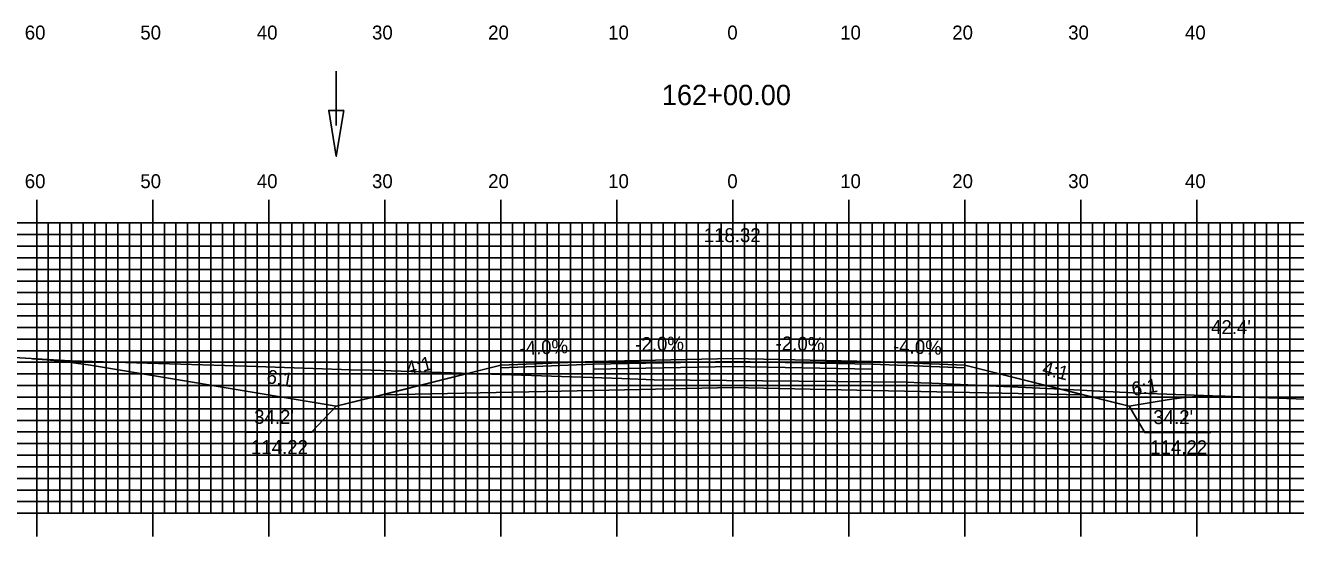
# Model space of a CAD drawing. Extents: x 1780286 to 1780629, y 442591 to 442811.
# Drawn here: x 1780390.9 to 1780500.4, y 442696.7 to 442740.7 of the extents above; entities that cross this region are included whole.
import ezdxf

# ---------------------------------------------------------------- set-up
doc = ezdxf.new("R2010")
doc.units = 0
for name, color, linetype in [('ANNOTATION', 7, 'Continuous'), ('D_Drainage_Ditch_Line', 7, 'Continuous'), ('D_Roadway_Centerline', 7, 'Continuous'), ('D_Roadway_Centerline_Text', 7, 'Continuous'), ('D_Roadway_Edge_Shoulder', 7, 'Continuous'), ('D_Roadway_Edge_TW', 7, 'Continuous'), ('D_Roadway_Pavement', 7, 'Continuous'), ('D_Roadway_SlopeLines', 7, 'Continuous'), ('D_Roadway_SubGrade', 7, 'Continuous'), ('D_Text_Standard', 7, 'Continuous'), ('H_V ANNOTATION', 7, 'Continuous'), ('MAJOR', 7, 'Continuous'), ('MINOR', 7, 'Continuous'), ('S_Roadway_Centerline', 7, 'Continuous')]:
    doc.layers.add(name, color=color, linetype=linetype)

msp = doc.modelspace()

# ---------------------------------------------------------------- linework, layer by layer
at = {"layer": 'ANNOTATION'}
for points in [[(1780409.87, 442705.65), (1780415.56, 442705.65), (1780417.69, 442707.88)], [(1780493.06, 442705.62), (1780487.37, 442705.62), (1780486.04, 442707.88)]]:
    msp.add_lwpolyline(points, dxfattribs=at)
at = {"layer": 'D_Drainage_Ditch_Line'}
msp.add_line((1780417.69, 442732.05), (1780417.69, 442736.75), dxfattribs=at)
msp.add_lwpolyline([(1780418.35, 442733.36), (1780417.04, 442733.36), (1780417.69, 442729.42)], close=True, dxfattribs=at)
at = {"layer": 'D_Roadway_Centerline'}
msp.add_lwpolyline([(1780391.5, 442711.98), (1780392.75, 442711.89), (1780394, 442711.77), (1780395.25, 442711.61), (1780396.5, 442711.42), (1780417.69, 442707.88), (1780421.69, 442708.88), (1780431.87, 442711.43), (1780439.87, 442711.75), (1780451.87, 442711.99), (1780463.87, 442711.75), (1780471.87, 442711.43), (1780482.04, 442708.88), (1780486.04, 442707.88), (1780489.29, 442708.43), (1780490.54, 442708.6), (1780491.79, 442708.72), (1780493.04, 442708.77), (1780494.29, 442708.75)], dxfattribs=at)
at = {"layer": 'D_Roadway_Edge_Shoulder'}
for points in [[(1780439.87, 442711.75), (1780431.87, 442711.43), (1780431.87, 442711.18), (1780439.87, 442711.5)], [(1780463.87, 442711.75), (1780471.87, 442711.43), (1780471.87, 442711.18), (1780463.87, 442711.5)]]:
    msp.add_lwpolyline(points, close=True, dxfattribs=at)
at = {"layer": 'D_Roadway_Edge_TW'}
msp.add_lwpolyline([(1780439.87, 442711.5), (1780439.87, 442711.75), (1780451.87, 442711.99), (1780463.87, 442711.75), (1780463.87, 442711.5), (1780451.87, 442711.74)], close=True, dxfattribs=at)
at = {"layer": 'D_Roadway_Pavement'}
msp.add_lwpolyline([(1780439.87, 442711.08), (1780439.87, 442711.5), (1780451.87, 442711.74), (1780463.87, 442711.5), (1780463.87, 442711.08), (1780451.87, 442711.32)], close=True, dxfattribs=at)
at = {"layer": 'D_Roadway_SlopeLines'}
for points in [[(1780417.69, 442707.88), (1780396.5, 442711.42), (1780395.25, 442711.61), (1780394, 442711.77), (1780392.75, 442711.89), (1780391.5, 442711.98)], [(1780431.87, 442711.43), (1780417.69, 442707.88)], [(1780471.87, 442711.43), (1780486.04, 442707.88)], [(1780486.04, 442707.88), (1780489.29, 442708.43), (1780490.54, 442708.6), (1780491.79, 442708.72), (1780493.04, 442708.77), (1780494.29, 442708.75)]]:
    msp.add_lwpolyline(points, dxfattribs=at)
at = {"layer": 'D_Roadway_SubGrade'}
msp.add_lwpolyline([(1780439.87, 442709.25), (1780421.69, 442708.88), (1780431.87, 442711.43), (1780431.87, 442711.18), (1780439.87, 442711.5), (1780451.87, 442711.74), (1780463.87, 442711.5), (1780471.87, 442711.18), (1780471.87, 442711.43), (1780482.04, 442708.88), (1780463.87, 442709.25), (1780451.87, 442709.49)], close=True, dxfattribs=at)
at = {"layer": 'MAJOR'}
for p, q in [((1780391.87, 442725.67), (1780391.87, 442723.67)), ((1780401.87, 442725.67), (1780401.87, 442723.67)), ((1780411.87, 442725.67), (1780411.87, 442723.67)), ((1780421.87, 442725.67), (1780421.87, 442723.67)), ((1780431.87, 442725.67), (1780431.87, 442723.67)), ((1780441.87, 442725.67), (1780441.87, 442723.67)), ((1780451.87, 442725.67), (1780451.87, 442723.67)), ((1780461.87, 442725.67), (1780461.87, 442723.67)), ((1780471.87, 442725.67), (1780471.87, 442723.67)), ((1780481.87, 442725.67), (1780481.87, 442723.67)), ((1780491.87, 442725.67), (1780491.87, 442723.67)), ((1780311.87, 442723.67), (1780591.87, 442723.67)), ((1780311.87, 442723.67), (1780591.87, 442723.67)), ((1780391.87, 442698.67), (1780391.87, 442723.67)), ((1780401.87, 442698.67), (1780401.87, 442723.67)), ((1780411.87, 442698.67), (1780411.87, 442723.67)), ((1780421.87, 442698.67), (1780421.87, 442723.67)), ((1780431.87, 442698.67), (1780431.87, 442723.67)), ((1780441.87, 442698.67), (1780441.87, 442723.67)), ((1780451.87, 442698.67), (1780451.87, 442723.67)), ((1780461.87, 442698.67), (1780461.87, 442723.67)), ((1780471.87, 442698.67), (1780471.87, 442723.67)), ((1780481.87, 442698.67), (1780481.87, 442723.67)), ((1780491.87, 442698.67), (1780491.87, 442723.67)), ((1780311.87, 442718.67), (1780591.87, 442718.67)), ((1780311.87, 442713.67), (1780591.87, 442713.67)), ((1780311.87, 442708.67), (1780591.87, 442708.67)), ((1780311.87, 442703.67), (1780591.87, 442703.67)), ((1780311.87, 442698.67), (1780591.87, 442698.67)), ((1780311.87, 442698.67), (1780591.87, 442698.67)), ((1780391.87, 442696.66), (1780391.87, 442698.67)), ((1780401.87, 442696.66), (1780401.87, 442698.67)), ((1780411.87, 442696.66), (1780411.87, 442698.67)), ((1780421.87, 442696.66), (1780421.87, 442698.67)), ((1780431.87, 442696.66), (1780431.87, 442698.67)), ((1780441.87, 442696.66), (1780441.87, 442698.67)), ((1780451.87, 442696.66), (1780451.87, 442698.67)), ((1780461.87, 442696.66), (1780461.87, 442698.67)), ((1780471.87, 442696.66), (1780471.87, 442698.67)), ((1780481.87, 442696.66), (1780481.87, 442698.67)), ((1780491.87, 442696.66), (1780491.87, 442698.67))]:
    msp.add_line(p, q, dxfattribs=at)
at = {"layer": 'MINOR'}
for p, q in [((1780392.87, 442698.67), (1780392.87, 442723.67)), ((1780393.87, 442698.67), (1780393.87, 442723.67)), ((1780394.87, 442698.67), (1780394.87, 442723.67)), ((1780395.87, 442698.67), (1780395.87, 442723.67)), ((1780396.87, 442698.67), (1780396.87, 442723.67)), ((1780397.87, 442698.67), (1780397.87, 442723.67)), ((1780398.87, 442698.67), (1780398.87, 442723.67)), ((1780399.87, 442698.67), (1780399.87, 442723.67)), ((1780400.87, 442698.67), (1780400.87, 442723.67)), ((1780402.87, 442698.67), (1780402.87, 442723.67)), ((1780403.87, 442698.67), (1780403.87, 442723.67)), ((1780404.87, 442698.67), (1780404.87, 442723.67)), ((1780405.87, 442698.67), (1780405.87, 442723.67)), ((1780406.87, 442698.67), (1780406.87, 442723.67)), ((1780407.87, 442698.67), (1780407.87, 442723.67)), ((1780408.87, 442698.67), (1780408.87, 442723.67)), ((1780409.87, 442698.67), (1780409.87, 442723.67)), ((1780410.87, 442698.67), (1780410.87, 442723.67)), ((1780412.87, 442698.67), (1780412.87, 442723.67)), ((1780413.87, 442698.67), (1780413.87, 442723.67)), ((1780414.87, 442698.67), (1780414.87, 442723.67)), ((1780415.87, 442698.67), (1780415.87, 442723.67)), ((1780416.87, 442698.67), (1780416.87, 442723.67)), ((1780417.87, 442698.67), (1780417.87, 442723.67)), ((1780418.87, 442698.67), (1780418.87, 442723.67)), ((1780419.87, 442698.67), (1780419.87, 442723.67)), ((1780420.87, 442698.67), (1780420.87, 442723.67)), ((1780422.87, 442698.67), (1780422.87, 442723.67)), ((1780423.87, 442698.67), (1780423.87, 442723.67)), ((1780424.87, 442698.67), (1780424.87, 442723.67)), ((1780425.87, 442698.67), (1780425.87, 442723.67)), ((1780426.87, 442698.67), (1780426.87, 442723.67)), ((1780427.87, 442698.67), (1780427.87, 442723.67)), ((1780428.87, 442698.67), (1780428.87, 442723.67)), ((1780429.87, 442698.67), (1780429.87, 442723.67)), ((1780430.87, 442698.67), (1780430.87, 442723.67)), ((1780432.87, 442698.67), (1780432.87, 442723.67)), ((1780433.87, 442698.67), (1780433.87, 442723.67)), ((1780434.87, 442698.67), (1780434.87, 442723.67)), ((1780435.87, 442698.67), (1780435.87, 442723.67)), ((1780436.87, 442698.67), (1780436.87, 442723.67)), ((1780437.87, 442698.67), (1780437.87, 442723.67)), ((1780438.87, 442698.67), (1780438.87, 442723.67)), ((1780439.87, 442698.67), (1780439.87, 442723.67)), ((1780440.87, 442698.67), (1780440.87, 442723.67)), ((1780442.87, 442698.67), (1780442.87, 442723.67)), ((1780443.87, 442698.67), (1780443.87, 442723.67)), ((1780444.87, 442698.67), (1780444.87, 442723.67)), ((1780445.87, 442698.67), (1780445.87, 442723.67)), ((1780446.87, 442698.67), (1780446.87, 442723.67)), ((1780447.87, 442698.67), (1780447.87, 442723.67)), ((1780448.87, 442698.67), (1780448.87, 442723.67)), ((1780449.87, 442698.67), (1780449.87, 442723.67)), ((1780450.87, 442698.67), (1780450.87, 442723.67)), ((1780452.87, 442698.67), (1780452.87, 442723.67)), ((1780453.87, 442698.67), (1780453.87, 442723.67)), ((1780454.87, 442698.67), (1780454.87, 442723.67)), ((1780455.87, 442698.67), (1780455.87, 442723.67)), ((1780456.87, 442698.67), (1780456.87, 442723.67)), ((1780457.87, 442698.67), (1780457.87, 442723.67)), ((1780458.87, 442698.67), (1780458.87, 442723.67)), ((1780459.87, 442698.67), (1780459.87, 442723.67)), ((1780460.87, 442698.67), (1780460.87, 442723.67)), ((1780462.87, 442698.67), (1780462.87, 442723.67)), ((1780463.87, 442698.67), (1780463.87, 442723.67)), ((1780464.87, 442698.67), (1780464.87, 442723.67)), ((1780465.87, 442698.67), (1780465.87, 442723.67)), ((1780466.87, 442698.67), (1780466.87, 442723.67)), ((1780467.87, 442698.67), (1780467.87, 442723.67)), ((1780468.87, 442698.67), (1780468.87, 442723.67)), ((1780469.87, 442698.67), (1780469.87, 442723.67)), ((1780470.87, 442698.67), (1780470.87, 442723.67)), ((1780472.87, 442698.67), (1780472.87, 442723.67)), ((1780473.87, 442698.67), (1780473.87, 442723.67)), ((1780474.87, 442698.67), (1780474.87, 442723.67)), ((1780475.87, 442698.67), (1780475.87, 442723.67)), ((1780476.87, 442698.67), (1780476.87, 442723.67)), ((1780477.87, 442698.67), (1780477.87, 442723.67)), ((1780478.87, 442698.67), (1780478.87, 442723.67)), ((1780479.87, 442698.67), (1780479.87, 442723.67)), ((1780480.87, 442698.67), (1780480.87, 442723.67)), ((1780482.87, 442698.67), (1780482.87, 442723.67)), ((1780483.87, 442698.67), (1780483.87, 442723.67)), ((1780484.87, 442698.67), (1780484.87, 442723.67)), ((1780485.87, 442698.67), (1780485.87, 442723.67)), ((1780486.87, 442698.67), (1780486.87, 442723.67)), ((1780487.87, 442698.67), (1780487.87, 442723.67)), ((1780488.87, 442698.67), (1780488.87, 442723.67)), ((1780489.87, 442698.67), (1780489.87, 442723.67)), ((1780490.87, 442698.67), (1780490.87, 442723.67)), ((1780492.87, 442698.67), (1780492.87, 442723.67)), ((1780493.87, 442698.67), (1780493.87, 442723.67)), ((1780494.87, 442698.67), (1780494.87, 442723.67)), ((1780495.87, 442698.67), (1780495.87, 442723.67)), ((1780496.87, 442698.67), (1780496.87, 442723.67)), ((1780497.87, 442698.67), (1780497.87, 442723.67)), ((1780498.87, 442698.67), (1780498.87, 442723.67)), ((1780499.87, 442698.67), (1780499.87, 442723.67)), ((1780311.87, 442722.67), (1780591.87, 442722.67)), ((1780311.87, 442721.67), (1780591.87, 442721.67)), ((1780311.87, 442720.67), (1780591.87, 442720.67)), ((1780311.87, 442719.67), (1780591.87, 442719.67)), ((1780311.87, 442717.67), (1780591.87, 442717.67)), ((1780311.87, 442716.67), (1780591.87, 442716.67)), ((1780311.87, 442715.67), (1780591.87, 442715.67)), ((1780311.87, 442714.67), (1780591.87, 442714.67)), ((1780311.87, 442712.67), (1780591.87, 442712.67)), ((1780311.87, 442711.67), (1780591.87, 442711.67)), ((1780311.87, 442710.67), (1780591.87, 442710.67)), ((1780311.87, 442709.67), (1780591.87, 442709.67)), ((1780311.87, 442707.67), (1780591.87, 442707.67)), ((1780311.87, 442706.67), (1780591.87, 442706.67)), ((1780311.87, 442705.67), (1780591.87, 442705.67)), ((1780311.87, 442704.67), (1780591.87, 442704.67)), ((1780311.87, 442702.67), (1780591.87, 442702.67)), ((1780311.87, 442701.67), (1780591.87, 442701.67)), ((1780311.87, 442700.67), (1780591.87, 442700.67)), ((1780311.87, 442699.67), (1780591.87, 442699.67))]:
    msp.add_line(p, q, dxfattribs=at)
at = {"layer": 'S_Roadway_Centerline'}
msp.add_lwpolyline([(1780389.46, 442712.1), (1780394.76, 442711.79), (1780409.99, 442711.34), (1780418.95, 442711.03), (1780420.71, 442710.98), (1780422.43, 442710.94), (1780442.29, 442710.27), (1780445.08, 442710.17), (1780466.88, 442709.95), (1780468.08, 442709.89), (1780469.02, 442709.86), (1780479.56, 442709.39), (1780486.9, 442709.02), (1780494.02, 442708.76), (1780503.64, 442708.4)], dxfattribs=at)

# ---------------------------------------------------------------- texts
at = {"layer": 'ANNOTATION'}
for s, rotation, p in [('-4.0%', 2.2906, (1780433.5, 442712.29)), ('-2.0%', 1.1458, (1780443.47, 442712.62)), ('-2.0%', 358.8542, (1780455.55, 442712.71)), ('-4.0%', 357.7094, (1780465.66, 442712.48)), ('4:1', 14.0362, (1780423.87, 442710.52)), ('6:1', 350.5377, (1780411.62, 442709.89)), ('4:1', 345.9638, (1780478.46, 442710.64)), ('6:1', 9.4625, (1780486.34, 442708.76))]:
    msp.add_text(s, height=1.2, rotation=rotation, dxfattribs=at).set_placement(p)
for s, p in [("34.2'", (1780410.61, 442706.37)), ("34.2'", (1780488.11, 442706.35)), ('114.22', (1780410.34, 442703.77)), ('114.22', (1780487.84, 442703.75))]:
    msp.add_text(s, height=1.2, dxfattribs=at).set_placement(p)
at = {"layer": 'D_Roadway_Centerline'}
for s, p in [('C', (1780451.86, 442711.99)), ('L', (1780451.87, 442711.98))]:
    msp.add_text(s, height=0.0146, dxfattribs=at).set_placement(p)
at = {"layer": 'D_Roadway_Centerline_Text'}
msp.add_text('118.32', height=1.2, dxfattribs=at).set_placement((1780449.36, 442722.02))
at = {"layer": 'D_Text_Standard'}
msp.add_text("42.4'", height=1.2, dxfattribs=at).set_placement((1780493.09, 442714.1))
at = {"layer": 'H_V ANNOTATION'}
for s, height, p in [('60', 1.2, (1780390.84, 442739.47)), ('50', 1.2, (1780400.8, 442739.47)), ('40', 1.2, (1780410.84, 442739.47)), ('30', 1.2, (1780420.77, 442739.47)), ('20', 1.2, (1780430.78, 442739.47)), ('10', 1.2, (1780441.12, 442739.47)), ('0', 1.2, (1780451.39, 442739.47)), ('10', 1.2, (1780461.12, 442739.47)), ('20', 1.2, (1780470.78, 442739.47)), ('30', 1.2, (1780480.77, 442739.47)), ('40', 1.2, (1780490.84, 442739.47)), ('162+00.00', 1.75, (1780445.75, 442733.82)), ('60', 1.2, (1780390.84, 442726.67)), ('50', 1.2, (1780400.8, 442726.67)), ('40', 1.2, (1780410.84, 442726.67)), ('30', 1.2, (1780420.77, 442726.67)), ('20', 1.2, (1780430.78, 442726.67)), ('10', 1.2, (1780441.12, 442726.67)), ('0', 1.2, (1780451.39, 442726.67)), ('10', 1.2, (1780461.12, 442726.67)), ('20', 1.2, (1780470.78, 442726.67)), ('30', 1.2, (1780480.77, 442726.67)), ('40', 1.2, (1780490.84, 442726.67))]:
    msp.add_text(s, height=height, dxfattribs=at).set_placement(p)

doc.saveas('drawing.dxf')
